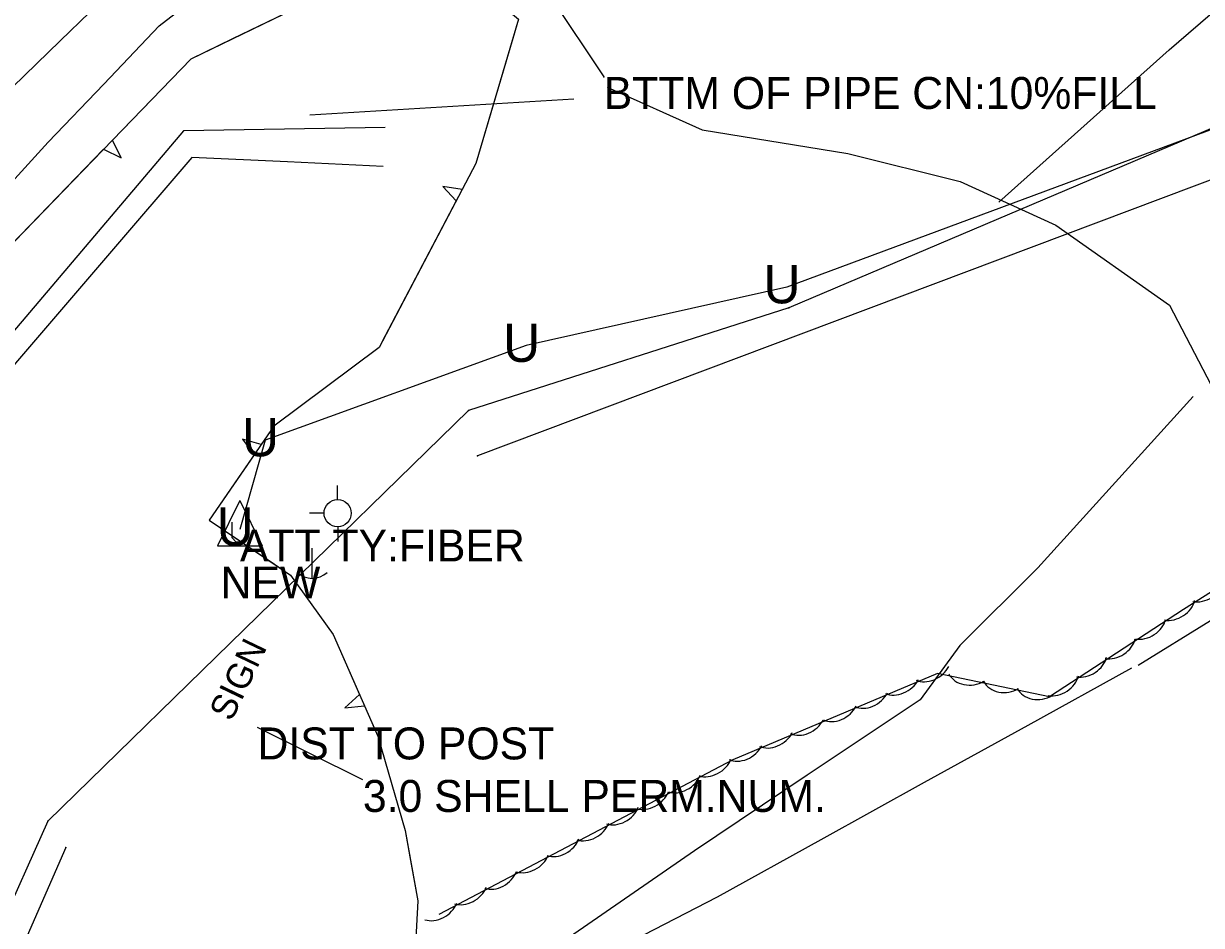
# Model space of a CAD drawing. Extents: x 978516 to 993312, y 1836504 to 1846212.
# Drawn here: x 981898.2 to 982082.5, y 1842173.5 to 1842314.6 of the extents above; entities that cross this region are included whole.
import ezdxf

# ---------------------------------------------------------------- set-up
doc = ezdxf.new("R2010")
doc.units = 0
for name, color, linetype in [('Default', 7, 'Continuous'), ('S_CROSS_DRAIN', 7, 'Continuous'), ('S_CROSS_DRAIN_ANNOT', 7, 'Continuous'), ('S_DITCHLINE', 7, 'Continuous'), ('S_DRG_PT_SYM', 7, 'Continuous'), ('S_DRIVEWAY', 7, 'Continuous'), ('S_EDGE_PAVEMENT', 7, 'Continuous'), ('S_GAS_UTILITIES', 7, 'Continuous'), ('S_GRAVEL_ROAD', 7, 'Continuous'), ('S_PAVEMENT_CROWN', 7, 'Continuous'), ('S_SIGN', 7, 'Continuous'), ('S_SIGN_ANNOT', 7, 'Continuous'), ('S_STREAM', 7, 'Continuous'), ('S_SURVEY_TEXT_ANNOT', 7, 'Continuous'), ('S_TREE', 7, 'Continuous'), ('S_UNDERGROUND_CABLE', 7, 'Continuous'), ('S_UTILITY_POLE', 7, 'Continuous'), ('S_UTILITY_POLE_ANNOT', 7, 'Continuous'), ('S_UTL_PT_SYM', 7, 'Continuous'), ('S_WATER_UTILITIES', 7, 'Continuous')]:
    doc.layers.add(name, color=color, linetype=linetype)

msp = doc.modelspace()

# ---------------------------------------------------------------- linework, layer by layer
at = {"layer": 'S_CROSS_DRAIN'}
msp.add_line((981921.1, 1842408.46), (981988.96, 1842306.27), dxfattribs=at)
at = {"layer": 'S_DITCHLINE'}
for points in [[(981989.52, 1842304.68), (982004.35, 1842298), (982027.16, 1842294.27), (982044.74, 1842289.92), (982059.71, 1842283.07), (982077.5, 1842270.55), (982084.64, 1842256.84)], [(981954.77, 1842298.36), (981938.99, 1842298.11), (981923.21, 1842297.86), (981909.85, 1842282.09), (981896.49, 1842266.32), (981883.12, 1842250.55), (981869.76, 1842234.79), (981860.26, 1842219.27), (981850.75, 1842203.75), (981841.24, 1842188.24), (981831.73, 1842172.72), (981822.76, 1842157.5), (981813.79, 1842142.28), (981804.82, 1842127.06), (981795.85, 1842111.84)], [(981954.43, 1842292.27), (981939.46, 1842292.97), (981924.48, 1842293.66), (981911.31, 1842278.29), (981898.14, 1842262.92), (981884.96, 1842247.55), (981871.79, 1842232.18), (981862.51, 1842216.67), (981853.22, 1842201.16), (981843.94, 1842185.65), (981834.65, 1842170.14), (981825.92, 1842155.07), (981817.18, 1842140.01), (981808.44, 1842124.94), (981799.7, 1842109.87)], [(982081.22, 1842256.26), (982069.07, 1842242.86), (982056.91, 1842229.46), (982044.72, 1842217.26), (982038.48, 1842208.77), (982020.82, 1842196.96), (982003.15, 1842185.15), (981984.28, 1842172.12), (981965.4, 1842159.08), (981951.81, 1842148.77), (981938.22, 1842138.47), (981932.21, 1842116.89), (981926.19, 1842095.32), (981920.18, 1842073.74), (981914.17, 1842052.16)]]:
    msp.add_lwpolyline(points, dxfattribs=at)
at = {"layer": 'S_DRG_PT_SYM'}
msp.add_lwpolyline([(981988.96, 1842306.27), (981988.96, 1842306.32), (981988.96, 1842306.27), (981988.91, 1842306.27), (981988.96, 1842306.27), (981988.96, 1842306.22), (981988.96, 1842306.27), (981989.01, 1842306.27)], dxfattribs=at)
at = {"layer": 'S_DRIVEWAY'}
msp.add_lwpolyline([(982241.1, 1842345.79), (982229.97, 1842346.52), (982228.46, 1842331.1), (982226.94, 1842315.69), (982218.76, 1842298.6), (982208.08, 1842292.09), (982197.4, 1842285.58), (982186.72, 1842279.07), (982176.04, 1842272.56), (982164.45, 1842266.64), (982152.85, 1842260.72), (982135.38, 1842251.42), (982117.91, 1842242.12), (982106.58, 1842235.13), (982095.26, 1842228.14), (982083.94, 1842221.14), (982072.62, 1842214.15)], dxfattribs=at)
at = {"layer": 'S_EDGE_PAVEMENT'}
msp.add_lwpolyline([(981885.19, 1842277.67), (981902.01, 1842296.08), (981910.71, 1842305.17), (981919.41, 1842314.26), (981938.44, 1842328.98), (981958.41, 1842343.82), (981970.26, 1842351.07), (981982.11, 1842358.31), (981993.21, 1842364.55), (982004.32, 1842370.78), (982016.91, 1842376.47), (982029.5, 1842382.15), (982043.87, 1842387.44), (982058.24, 1842392.73), (982076.32, 1842397.03), (982094.41, 1842401.33), (982115.96, 1842404.98), (982137.51, 1842408.63), (982156.03, 1842411.26), (982174.56, 1842413.9), (982192.9, 1842417.94), (982211.24, 1842421.98), (982232.95, 1842431.69), (982241.11, 1842434.82)], dxfattribs=at)
at = {"layer": 'S_GAS_UTILITIES'}
for p, q in [((982124.16, 1842305.32), (981969.21, 1842246.97)), ((981904.79, 1842185.67), (981884.62, 1842139.62))]:
    msp.add_line(p, q, dxfattribs=at)
at = {"layer": 'S_GRAVEL_ROAD'}
msp.add_lwpolyline([(982071.55, 1842213.74), (982055.35, 1842204.78), (982039.14, 1842195.81), (982022.94, 1842186.84), (982006.74, 1842177.87), (981988.62, 1842168.54), (981970.5, 1842159.2), (981955.55, 1842146.95), (981940.6, 1842134.69), (981935.43, 1842113.71), (981930.27, 1842092.72), (981925.1, 1842071.73), (981919.93, 1842050.74)], dxfattribs=at)
at = {"layer": 'S_PAVEMENT_CROWN'}
msp.add_lwpolyline([(981894.59, 1842302.89), (981903.89, 1842311.91), (981913.19, 1842320.93), (981923.12, 1842329.22), (981933.05, 1842337.52), (981953.36, 1842351.56), (981965.29, 1842358.83), (981977.21, 1842366.11), (981989.16, 1842372.7), (982001.11, 1842379.29), (982013.44, 1842385.15), (982025.77, 1842391.01), (982040.52, 1842396.23), (982055.27, 1842401.44), (982074.2, 1842406.42), (982093.14, 1842411.4), (982114.31, 1842415.12), (982135.49, 1842418.84), (982154.43, 1842421.95), (982173.38, 1842425.06), (982190.17, 1842428.74), (982206.97, 1842432.41), (982228.48, 1842442.3), (982240.72, 1842452.48)], dxfattribs=at)
at = {"layer": 'S_SIGN'}
msp.add_line((981951.27, 1842196.23), (981934.78, 1842204.45), dxfattribs=at)
at = {"layer": 'S_STREAM'}
for points in [[(982050.79, 1842286.7), (982077.44, 1842310.52), (982098.2, 1842328.47), (982133.89, 1842357.21)], [(981942.97, 1842300.36), (981984.27, 1842302.85)]]:
    msp.add_lwpolyline(points, dxfattribs=at)
at = {"layer": 'S_TREE'}
for p, q in [((981913.42, 1842293.63), (981912.07, 1842296.37)), ((981910.7, 1842294.96), (981913.42, 1842293.63)), ((981966.79, 1842288.64), (981963.8, 1842289.14)), ((981963.8, 1842289.14), (981965.88, 1842286.9)), ((981935.37, 1842248.76), (981932.43, 1842249.57)), ((981932.43, 1842249.57), (981934.26, 1842247.14)), ((981950.76, 1842209.62), (981948.45, 1842207.51)), ((981948.45, 1842207.51), (981951.54, 1842207.84))]:
    msp.add_line(p, q, dxfattribs=at)
for points in [[(981889, 1842272.58), (981924.42, 1842309.12), (981940.44, 1842316.89), (981967.45, 1842322.21), (981975.63, 1842315.33), (981968.94, 1842292.73), (981953.81, 1842263.91), (981937.35, 1842251.62), (981927.2, 1842236.9), (981939.94, 1842228.31), (981946.63, 1842218.99), (981953.63, 1842203.09), (981957.9, 1842188.3), (981959.86, 1842177.3), (981958.98, 1842160.66)], [(981956.53, 1842320.06), (981967.45, 1842322.21), (981975.63, 1842315.33), (981974.72, 1842312.28)], [(981930.94, 1842312.29), (981940.44, 1842316.89), (981954.6, 1842319.68)], [(981912.07, 1842296.37), (981924.42, 1842309.12), (981930.94, 1842312.29)], [(981974.72, 1842312.28), (981968.94, 1842292.73), (981966.79, 1842288.64)], [(981893.3, 1842277.01), (981910.7, 1842294.96)], [(981965.88, 1842286.9), (981954.26, 1842264.77)], [(981954.26, 1842264.77), (981953.81, 1842263.91), (981937.35, 1842251.62), (981935.37, 1842248.76)], [(982140.68, 1842261.44), (982079.7, 1842222.9), (982058.74, 1842209.24), (982041.18, 1842212.9), (982009.16, 1842199.36), (981963.16, 1842175.19)], [(981934.26, 1842247.14), (981927.2, 1842236.9), (981937.44, 1842229.99)], [(981937.44, 1842229.99), (981939.94, 1842228.31), (981946.63, 1842218.99), (981950.76, 1842209.62)], [(981951.54, 1842207.84), (981953.63, 1842203.09), (981957.9, 1842188.3), (981958.63, 1842184.2)], [(981958.63, 1842184.2), (981959.86, 1842177.3), (981958.98, 1842160.66), (981958.43, 1842159.68)]]:
    msp.add_lwpolyline(points, dxfattribs=at)
for centre, major_axis, ratio, start_param, end_param in [((982082.55, 1842227.12), (3.17, 1.79), 0.767888, 3.891906, 5.665107), ((982078.06, 1842224.24), (3.16, 1.81), 0.76811, 3.900246, 5.673446), ((982073.51, 1842221.27), (3.16, 1.81), 0.76811, 3.900246, 5.673446), ((982068.76, 1842218.21), (3.16, 1.81), 0.76811, 3.900246, 5.673446), ((982064.27, 1842215.35), (3.16, 1.81), 0.76811, 3.900246, 5.673446), ((982039.96, 1842214.67), (2.99, 2.08), 0.758429, 3.552879, 5.326079), ((982035.19, 1842212.59), (2.99, 2.08), 0.758429, 3.552879, 5.326079), ((982046.29, 1842214.18), (3.63, 0.29), 0.852027, 3.495234, 5.268434), ((982051.73, 1842213.02), (3.63, 0.29), 0.852027, 3.495234, 5.268434), ((982059.88, 1842212.42), (3.16, 1.81), 0.76811, 3.900246, 5.673446), ((982030.38, 1842210.53), (2.99, 2.08), 0.758429, 3.552879, 5.326079), ((982056.98, 1842211.92), (3.63, 0.29), 0.852027, 3.495234, 5.268434), ((982025.45, 1842208.44), (2.99, 2.08), 0.758429, 3.552879, 5.326079), ((982020.32, 1842206.3), (2.99, 2.08), 0.758429, 3.552879, 5.326079), ((982015.47, 1842204.31), (2.99, 2.08), 0.758429, 3.552879, 5.326079), ((982010.69, 1842202.24), (2.99, 2.08), 0.758429, 3.552879, 5.326079), ((982005.7, 1842199.82), (3, 2.07), 0.763453, 3.669997, 5.443198), ((982000.9, 1842197.3), (3, 2.07), 0.763453, 3.669997, 5.443198), ((981995.92, 1842194.71), (3, 2.07), 0.763453, 3.669997, 5.443198), ((981991.2, 1842192.29), (3, 2.07), 0.763453, 3.669997, 5.443198), ((981986.57, 1842189.8), (3, 2.07), 0.763453, 3.669997, 5.443198), ((981981.91, 1842187.32), (3, 2.07), 0.763453, 3.669997, 5.443198), ((981977.11, 1842184.8), (3, 2.07), 0.763453, 3.669997, 5.443198), ((981972.13, 1842182.21), (3, 2.07), 0.763453, 3.669997, 5.443198), ((981967.41, 1842179.79), (3, 2.07), 0.763453, 3.669997, 5.443198), ((981962.78, 1842177.29), (3, 2.07), 0.763453, 3.669997, 5.443198)]:
    msp.add_ellipse(centre, major_axis=major_axis, ratio=ratio, start_param=start_param, end_param=end_param, dxfattribs=at)
at = {"layer": 'S_UNDERGROUND_CABLE'}
for p, q in [((982088.17, 1842299.54), (982017.6, 1842273.39)), ((982017.6, 1842273.39), (981976.85, 1842264.22)), ((981976.85, 1842264.22), (981935.98, 1842249.43)), ((981935.98, 1842249.43), (981932.03, 1842235.43)), ((981932.03, 1842239.97), (981928.5, 1842232.88)), ((981932.03, 1842239.97), (981935.52, 1842232.88)), ((981930.83, 1842234.12), (981930.83, 1842236.56)), ((981933.19, 1842236.56), (981933.19, 1842234.12)), ((981931.45, 1842233.46), (981930.83, 1842234.12)), ((981933.19, 1842234.12), (981932.65, 1842233.46)), ((981928.5, 1842232.88), (981935.52, 1842232.88)), ((981932.65, 1842233.46), (981931.45, 1842233.46))]:
    msp.add_line(p, q, dxfattribs=at)
at = {"layer": 'S_UTILITY_POLE'}
for p, q in [((981947.32, 1842240.1), (981947.32, 1842242.35)), ((981945.23, 1842237.97), (981942.9, 1842237.97)), ((981947.4, 1842233.55), (981947.4, 1842235.88)), ((981943.28, 1842232.51), (981943.28, 1842227.78))]:
    msp.add_line(p, q, dxfattribs=at)
msp.add_circle((981947.32, 1842237.99), 2.13, dxfattribs=at)
msp.add_arc((981943.34, 1842231.2), 3.41, 226.3972, 313.6028, dxfattribs=at)
at = {"layer": 'S_UTL_PT_SYM'}
for points in [[(982017.95, 1842270.14), (982017.95, 1842270.19), (982017.95, 1842270.14), (982017.9, 1842270.14), (982017.95, 1842270.14), (982017.95, 1842270.09), (982017.95, 1842270.14), (982018, 1842270.14)], [(981967.78, 1842254.08), (981967.78, 1842254.13), (981967.78, 1842254.08), (981967.73, 1842254.08), (981967.78, 1842254.08), (981967.78, 1842254.03), (981967.78, 1842254.08), (981967.83, 1842254.08)], [(981967.78, 1842254.08), (981967.78, 1842254.13), (981967.78, 1842254.08), (981967.73, 1842254.08), (981967.78, 1842254.08), (981967.78, 1842254.03), (981967.78, 1842254.08), (981967.83, 1842254.08)], [(981969.21, 1842246.97), (981969.21, 1842247.02), (981969.21, 1842246.97), (981969.16, 1842246.97), (981969.21, 1842246.97), (981969.21, 1842246.92), (981969.21, 1842246.97), (981969.26, 1842246.97)], [(981901.98, 1842189.77), (981901.98, 1842189.82), (981901.98, 1842189.77), (981901.93, 1842189.77), (981901.98, 1842189.77), (981901.98, 1842189.72), (981901.98, 1842189.77), (981902.03, 1842189.77)], [(981901.98, 1842189.77), (981901.98, 1842189.82), (981901.98, 1842189.77), (981901.93, 1842189.77), (981901.98, 1842189.77), (981901.98, 1842189.72), (981901.98, 1842189.77), (981902.03, 1842189.77)], [(981904.79, 1842185.67), (981904.79, 1842185.72), (981904.79, 1842185.67), (981904.74, 1842185.67), (981904.79, 1842185.67), (981904.79, 1842185.62), (981904.79, 1842185.67), (981904.84, 1842185.67)]]:
    msp.add_lwpolyline(points, dxfattribs=at)
at = {"layer": 'S_WATER_UTILITIES'}
for p, q in [((982091.04, 1842301.19), (982017.95, 1842270.14)), ((982017.95, 1842270.14), (981967.78, 1842254.08)), ((981967.78, 1842254.08), (981901.98, 1842189.77)), ((981901.98, 1842189.77), (981882.1, 1842145.52))]:
    msp.add_line(p, q, dxfattribs=at)

# ---------------------------------------------------------------- texts
at = {"layer": 'Default'}
for p in [(982013.97, 1842270.84), (981973.22, 1842261.67), (981932.35, 1842246.89), (981928.4, 1842232.89)]:
    msp.add_text('U', height=6, dxfattribs=at).set_placement(p)
at = {"layer": 'S_CROSS_DRAIN_ANNOT'}
msp.add_text('BTTM OF PIPE CN:10%FILL', height=5, dxfattribs=at).set_placement((981988.96, 1842301.27))
at = {"layer": 'S_SIGN_ANNOT'}
msp.add_text('SIGN', height=4, rotation=64.3321, dxfattribs=at).set_placement((981930.69, 1842205.24))
for s, p in [('DIST TO POST', (981934.78, 1842199.45)), ('3.0 SHELL PERM.NUM.', (981951.27, 1842191.23))]:
    msp.add_text(s, height=5, dxfattribs=at).set_placement(p)
at = {"layer": 'S_SURVEY_TEXT_ANNOT'}
msp.add_text('NEW', height=5, dxfattribs=at).set_placement((981929.01, 1842224.64))
at = {"layer": 'S_UTILITY_POLE_ANNOT'}
msp.add_text('ATT TY:FIBER', height=5, dxfattribs=at).set_placement((981932.03, 1842230.43))

doc.saveas('drawing.dxf')
